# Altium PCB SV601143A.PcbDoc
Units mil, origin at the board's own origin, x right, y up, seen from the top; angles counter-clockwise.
Board outline 3000 x 3000 mil, 4 copper layers (Top Layer, MidLayer1, MidLayer2, Bottom Layer), stack 62 mil thick; 53 components, 12 nets, 84 pads, 38 vias.
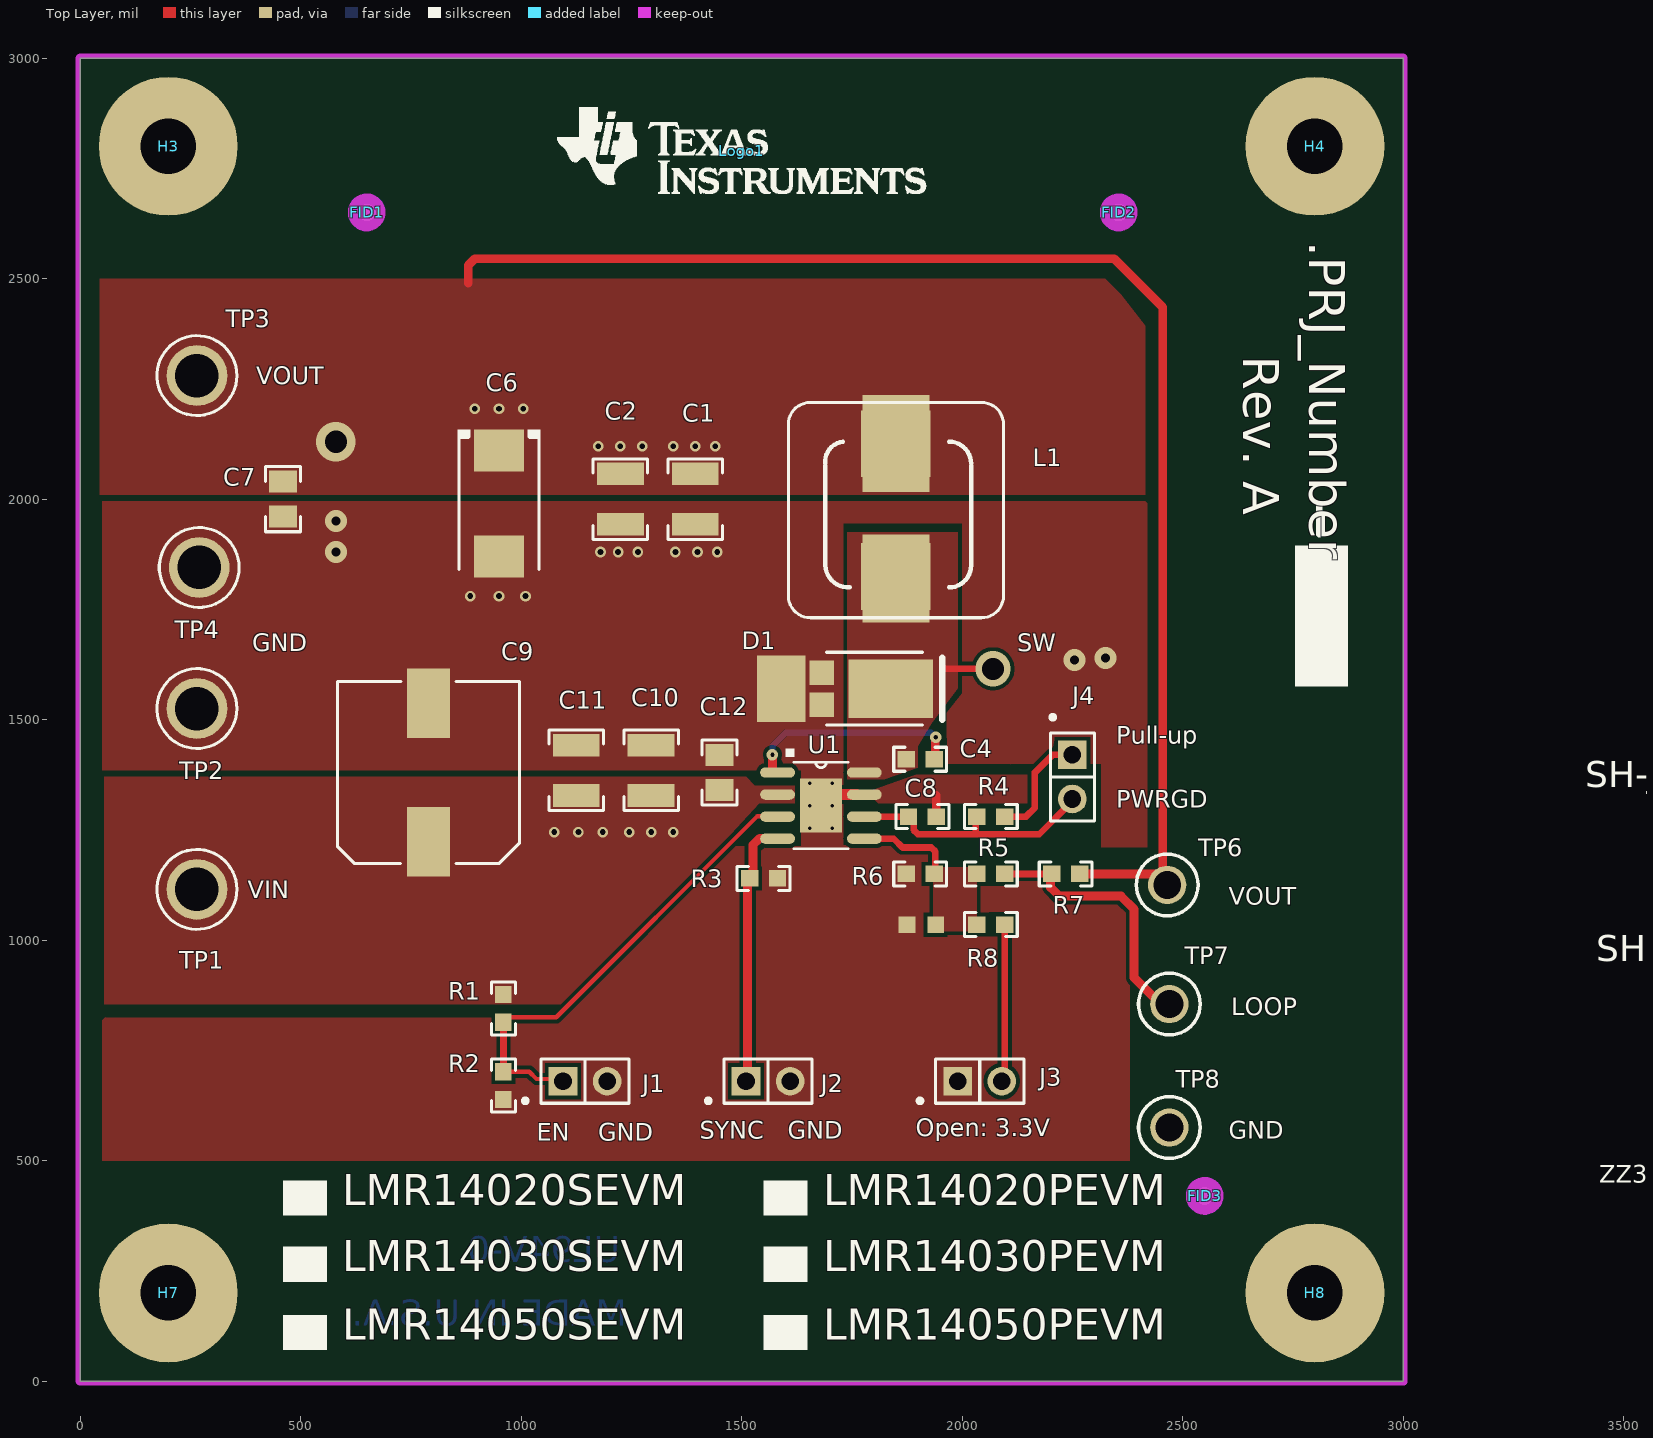
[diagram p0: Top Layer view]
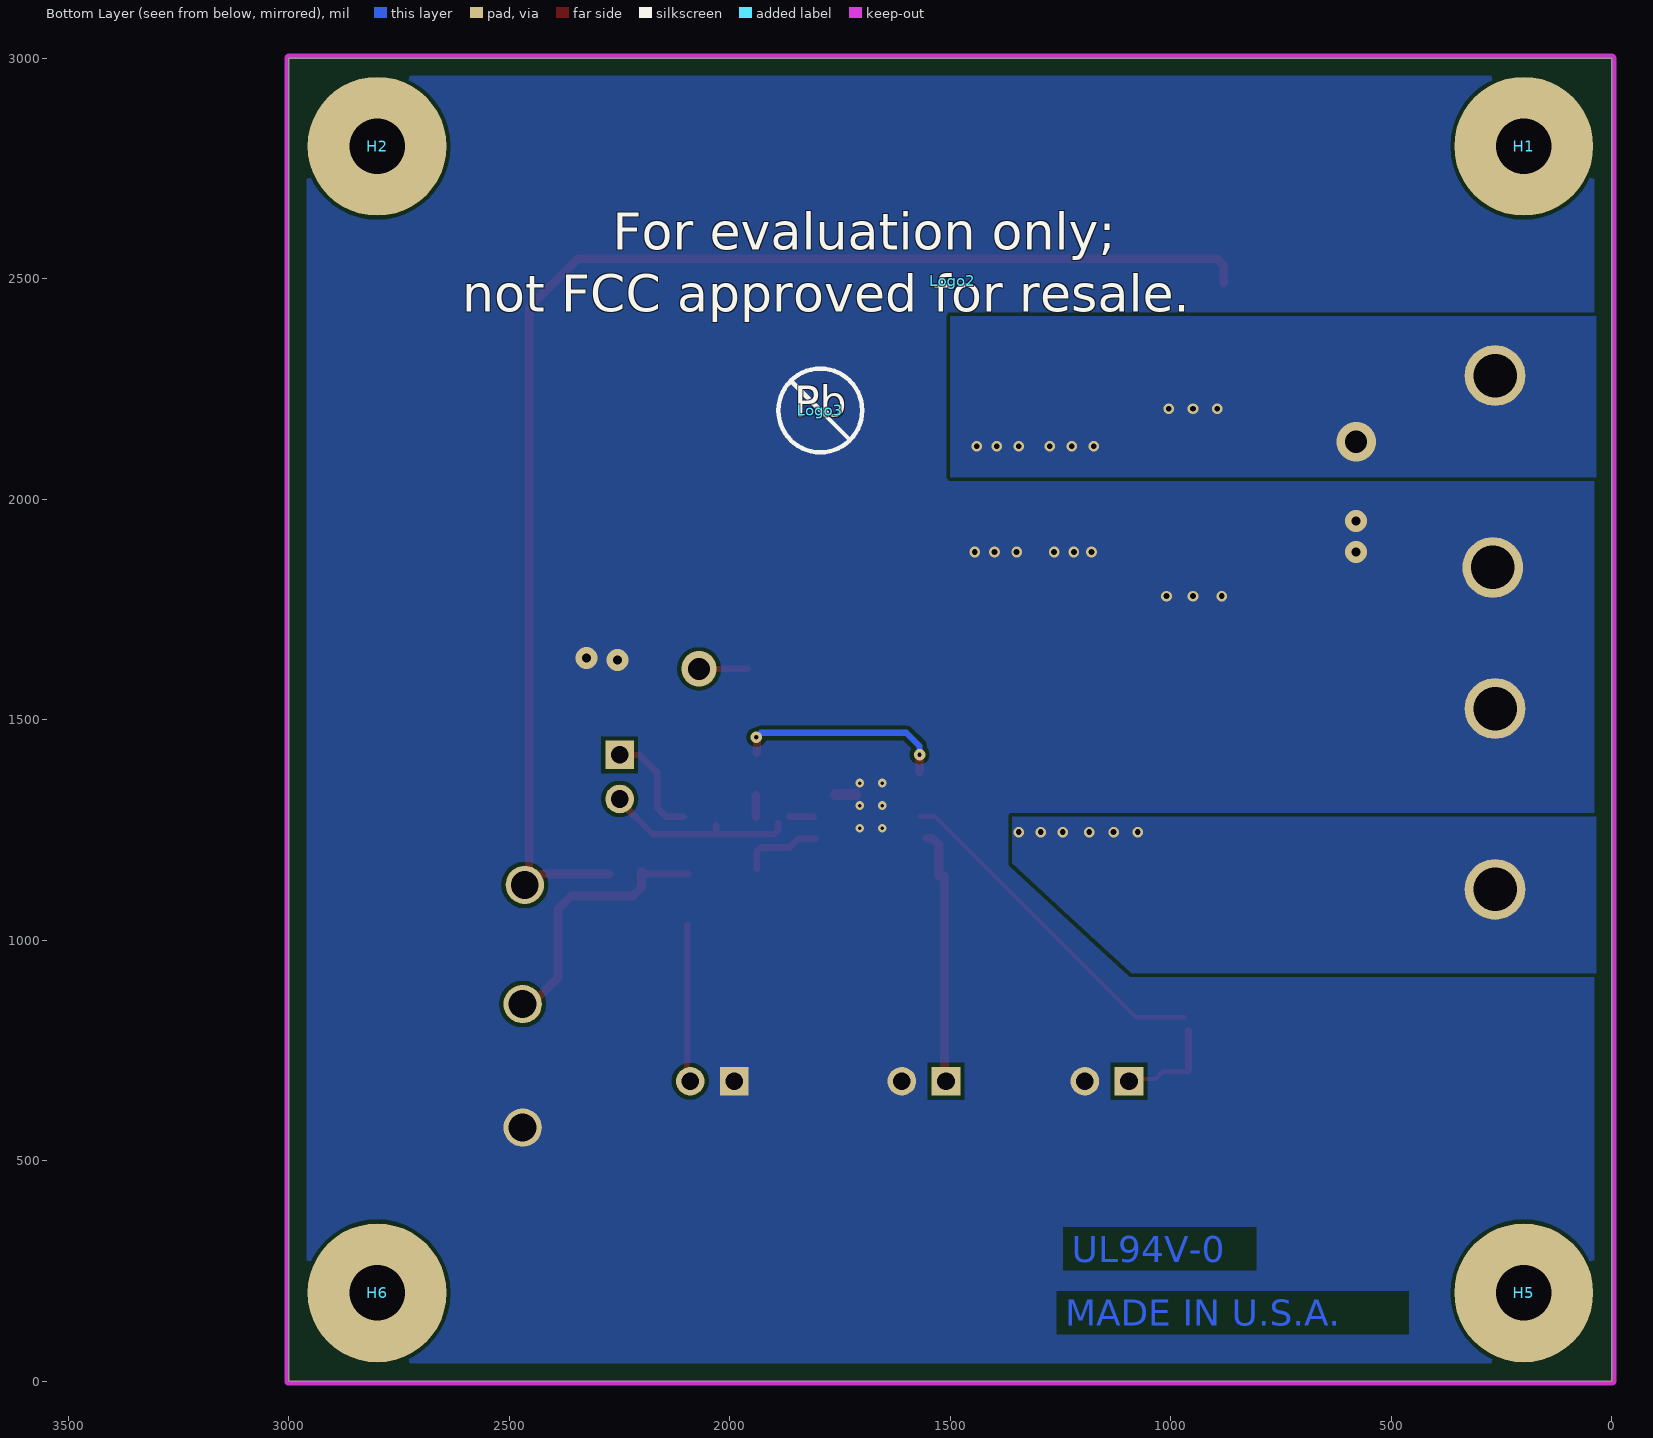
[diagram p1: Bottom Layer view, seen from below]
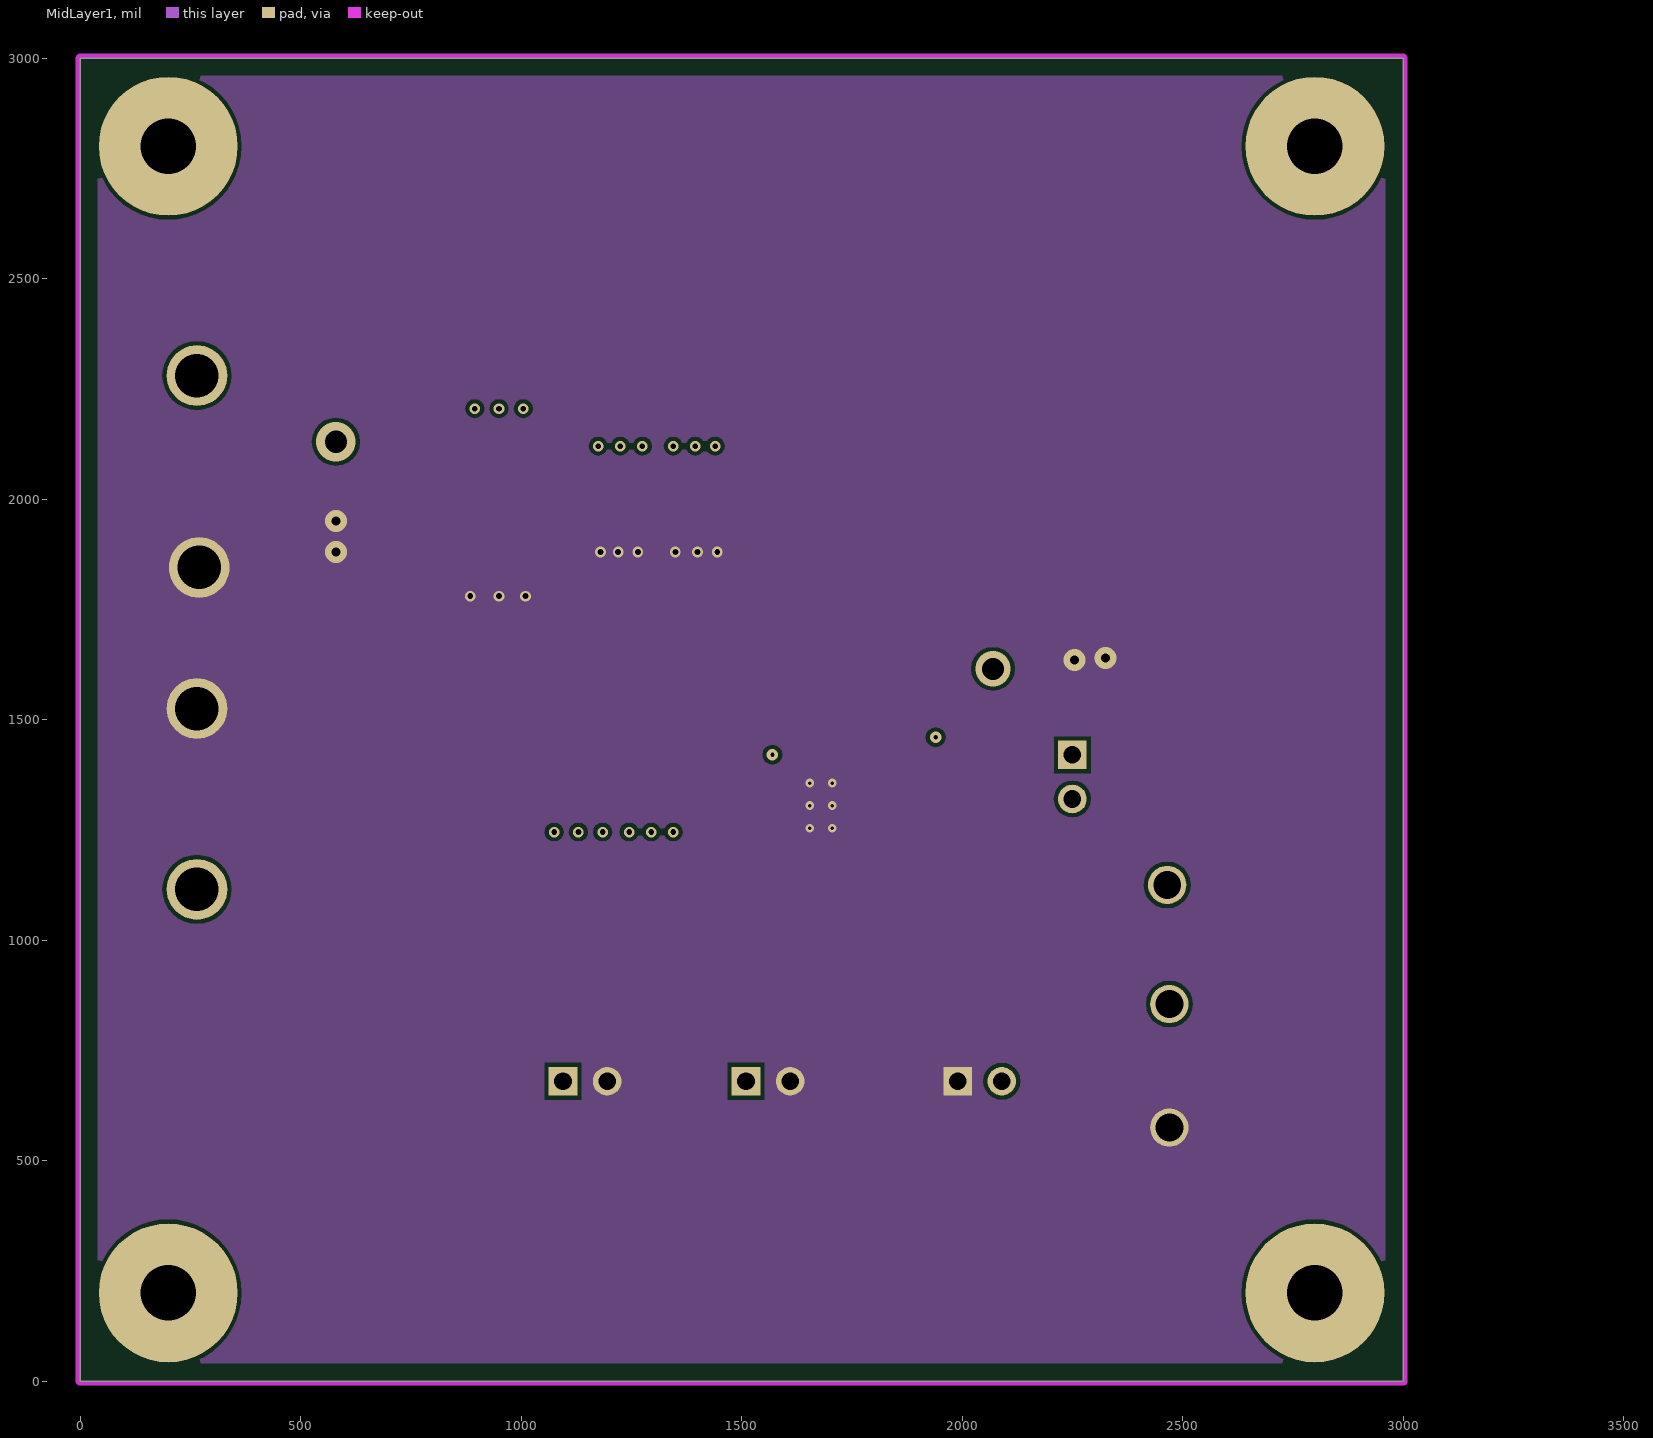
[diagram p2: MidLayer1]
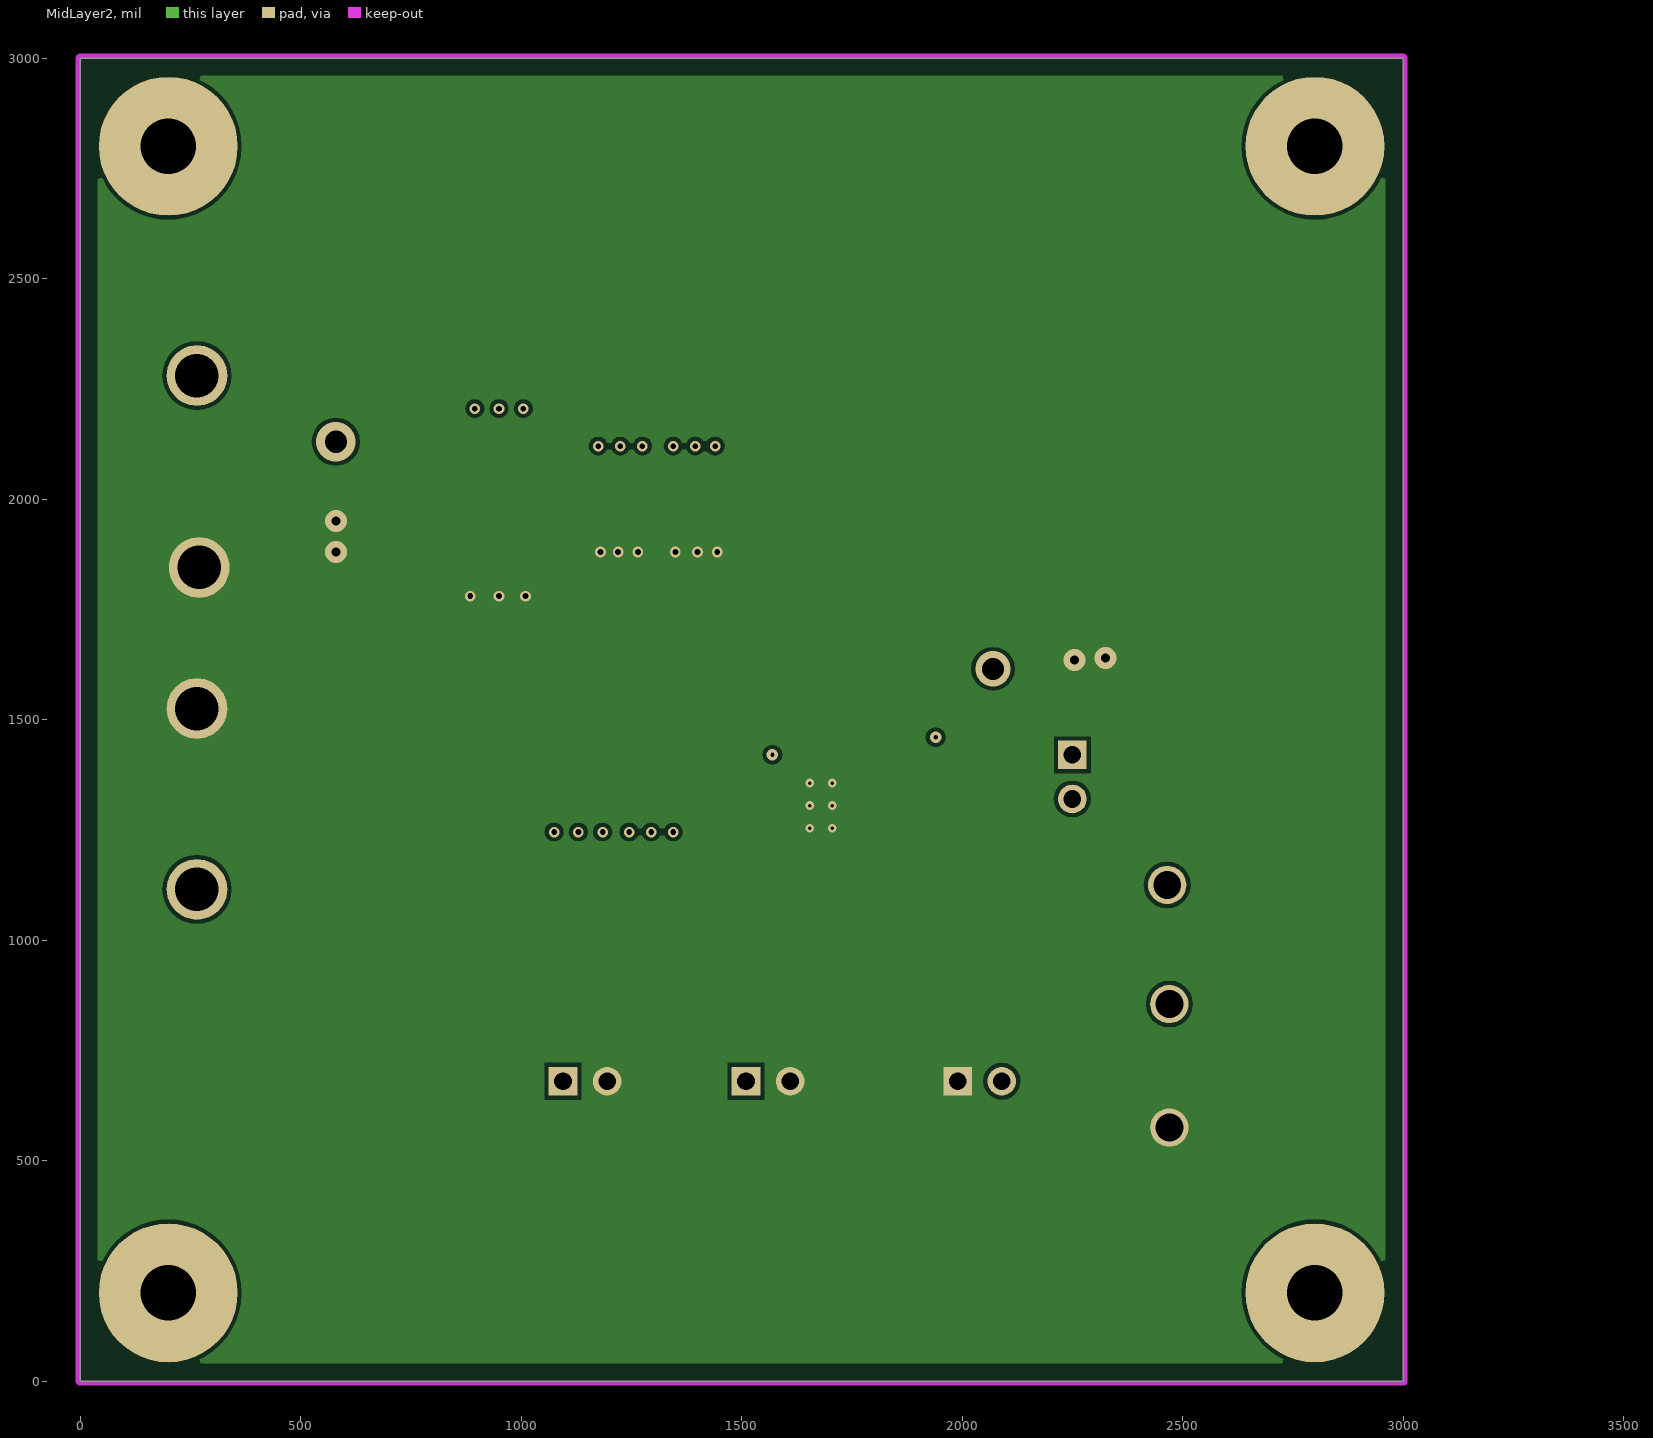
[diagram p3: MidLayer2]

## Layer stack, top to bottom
Top Layer: signal copper 2.8
Dielectric: core 16.9, FR-4, Dk 4.8
MidLayer1: signal copper 2.8
Dielectric: prepreg 17, FR-4, Dk 4.8
MidLayer2: signal copper 2.8
Dielectric: core 16.9, FR-4, Dk 4.8
Bottom Layer: signal copper 2.8

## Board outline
0,0 3000,0 3000,3000 0,3000

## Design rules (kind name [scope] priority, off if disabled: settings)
AcuteAngle [All] p1: minimum=4.50000000000000E+0001 checktracksonly=FALSE
AssemblyTestPointUsage [All] p1: valid=2
Clearance Clearance_1 [InNamedPolygon('Top-VOUT')] p1: gap=15
Clearance Clearance_BoardEdge_MountingHoles [OnCopper and InComponentClass('Mounting Holes') vs IsKeepOut] p2: gap=40
Clearance Clearance_BoardEdge_Poly [OnCopper and InPoly vs IsKeepOut] p3: gap=25
Clearance Clearance_BoardEdge [OnCopper and Not InComponentClass('Logo') and not InComponentClass('FiducialMark') and not InRegion(1000,500,4000,800) vs IsKeepOut] p4: gap=75
Clearance [All] p5: gap=9
ComponentClearance ComponentClearance_Logo [InComponentClass(Logo)] p1: gap=50 collisioncheckmode=3 verticalgap=10 showdistances=FALSE
ComponentClearance ComponentClearance_ScrewToNut [(HasFootprint('NY PMS 440 0025 PH')) vs (HasFootprint('Keystone_1902C'))] p2: gap=5 collisioncheckmode=3 verticalgap=10 showdistances=FALSE
ComponentClearance ComponentClearance_MountingHoles [InComponentClass('Mounting Holes')] p3: gap=0 collisioncheckmode=3 verticalgap=100000 showdistances=FALSE
ComponentClearance ComponentClearance_SmallPassives [HasFootprint('0201*') or HasFootprint('0402*') or HasFootprint('0508') or HasFootprint('0603*') or HasFootprint('0612') or HasFootprint('0805*') or HasFootprint('0815*') or HasFootprint('0830*') or HasFootprint('1206*') or HasFootprint('1210*') or HasFootprint('1808*') or HasFootprint('1812*') or HasFootprint('1825*') or HasFootprint('2010*') or HasFootprint('2220*') or HasFootprint('2225*') or HasFootprint('2512*') or HasFootprint('2728*') or HasFootprint('3518*') vs HasFootprint('0201*') or HasFootprint('0402*') or HasFootprint('0508') or HasFootprint('0603*') or HasFootprint('0612') or HasFootprint('0805*') or HasFootprint('0815*') or HasFootprint('0830*') or HasFootprint('1206*') or HasFootprint('1210*') or HasFootprint('1808*') or HasFootprint('1812*') or HasFootprint('1825*') or HasFootprint('2010*') or HasFootprint('2220*') or HasFootprint('2225*') or HasFootprint('2512*') or HasFootprint('2728*') or HasFootprint('3518*')] p4: gap=20 collisioncheckmode=3 verticalgap=10 showdistances=FALSE
ComponentClearance ComponentClearance_THtoSMT [IsThruComponent vs IsSMTComponent] p5: gap=25 collisioncheckmode=3 verticalgap=100000 showdistances=TRUE
ComponentClearance ComponentClearance_THtoTH [IsThruComponent vs IsThruComponent] p6: gap=15 collisioncheckmode=3 verticalgap=100000 showdistances=TRUE
ComponentClearance [All] p7: gap=0 collisioncheckmode=3 verticalgap=10 showdistances=FALSE
DiffPairsRouting [All] p1: maxlimit=100 minlimit=10 mostfreqgap=10 maxuncoupledlength=1000
FabricationTestPointUsage TestPointUsage [All] p1: valid=2 allowmultiple=FALSE
FabricationTestpoint Testpoint [All] p1: side=3 testpointundercomponent=TRUE minsize=40 maxsize=100 preferedsize=60 minholesize=0 maxholesize=40 preferedholesize=32 testpointgrid=1 allowsidetop=TRUE allowsidebottom=TRUE usegrid=TRUE gridtolerance=0.01
FanoutControl Fanout_LCC [IsLCC] p1: bgadir=Out bgaviamode=Centered fanoutstyle=Auto fanoutdirection=Alternating viagrid=1 // Fanout_LCC (Default Rule)
FanoutControl Fanout_BGA [IsBGA] p2: bgadir=Out bgaviamode=Centered fanoutstyle=Auto fanoutdirection=Alternating viagrid=1 // Fanout_BGA (Default Rule)
FanoutControl Fanout_Default [All] p4: bgadir=Out bgaviamode=Centered fanoutstyle=Auto fanoutdirection=Alternating viagrid=1 // Fanout_Default (Default Rule)
FanoutControl Fanout_Small [(CompPinCount < 5)] p5: bgadir=Out bgaviamode=Centered fanoutstyle=Auto fanoutdirection=OutThenIn viagrid=1 // Fanout_Small (Default Rule)
HoleSize [All] p1: absolutevalues=TRUE maxlimit=251 minlimit=7.8 maxpercent=80.000 minpercent=20.000
MinimumAnnularRing [All] p1: minimumring=5.5
MinimumSolderMaskSliver MinimumSolderMaskSliver_Logo [InComponentClass('Logo') vs InComponentClass('Logo')] p1: minsoldermaskwidth=0.7
MinimumSolderMaskSliver [All] p2: minsoldermaskwidth=5
PlaneConnect [All] p1: planeconnectstyle=Direct reliefexpansion=20 reliefentries=4 reliefconductorwidth=10 reliefairgap=10
PolygonConnect [All] p1: connectstyle=Direct reliefconductorwidth=10 reliefentries=4 polygonreliefangle="90 Angle" airgapwidth=10
RoutingVias [All] p1: holewidth=16 width=34 viastyle="Through Hole" minholewidth=7.8 minwidth=19 maxholewidth=50 maxwidth=90
SMDToCorner [All] p1: distance=30000
SilkToSilkClearance [All] p1: silktosilkclearance=5
SilkscreenOverComponentPads [All] p1: minsilkscreentomaskgap=5
SolderMaskExpansion [All] p1: expansion=1
Width [All] p1: maxlimit=100 minlimit=8 preferedwidth=10 checkconnectedcopper=TRUE
14 further rules are at their usual default settings.

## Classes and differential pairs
component class Shunt: SH-J1 SH-J3
component class Header: J1 J2 J3 J4
component class AssemblyNote: ZZ1 ZZ2 ZZ4 ZZ5
component class FiducialMark: FID1 FID2 FID3
component class Logo: Logo1
component class "Mounting Holes": H3 H4 H7 H8

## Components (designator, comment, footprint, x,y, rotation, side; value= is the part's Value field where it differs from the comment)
C1 "GRM32ER61C476ME15L" 1210 1395,2000 r270 top
C2 "GRM32ER61C476ME15L" 1210 1225,2000 r270 top
C4 "GRM188R71C104KA01D" 0603 1905,1410 r0 top
C6 "16TQC150MYF" 7343-28 950,1990 r270 top
C7 "GRM21BR71E105KA99L" 0805_HV 460,2000 r270 top
C8 "C0603C273K1RACTU" 0603 1910,1280 r0 top
C9 "EEHZA1J560P" SM_RADIAL_10BMM 790,1380 r90 top
C10 "GRM32ER71H475KA88L" 1210 1295,1385 r90 top
C11 "GRM32ER71H475KA88L" 1210 1125,1385 r90 top
C12 "GRM21BR71H224KA01L" 0805_HV 1450,1380 r90 top
D1 "PDS560-13" PowerDI5 1760,1570 r0 top
FID1 "Fiducial" Fiducial10-20 650,2650 r0 top
FID2 "Fiducial" Fiducial10-20 2355,2650 r0 top
FID3 "Fiducial" Fiducial10-20 2550,420 r0 top
H1 "1902C" Keystone_1902C 200,2800 r180 bottom locked
H2 "1902C" Keystone_1902C 2800,2800 r180 bottom locked
H3 "NY PMS 440 0025 PH" "NY PMS 440 0025 PH" 200,2800 r0 top locked
H4 "NY PMS 440 0025 PH" "NY PMS 440 0025 PH" 2800,2800 r0 top locked
H5 "1902C" Keystone_1902C 200,200 r180 bottom locked
H6 "1902C" Keystone_1902C 2800,200 r180 bottom locked
H7 "NY PMS 440 0025 PH" "NY PMS 440 0025 PH" 200,200 r0 top locked
H8 "NY PMS 440 0025 PH" "NY PMS 440 0025 PH" 2800,200 r0 top locked
J1 "TSW-102-07-G-S" TSW-102-07-G-S 1145,680 r0 top
J2 "TSW-102-07-G-S" TSW-102-07-G-S 1560,680 r0 top
J3 "TSW-102-07-G-S" TSW-102-07-G-S 2040,680 r0 top
J4 "TSW-102-07-G-S" TSW-102-07-G-S 2250,1370 r270 top
L1 "744325550" WE-HC6 1850,1975 r90 top
Logo1 "Texas Instruments" TI_Stacked_Overlay_Small 1500,2790 r0 top
Logo2 "FCC disclaimer" FCC_disclaimer_stacked 1495,2495 r180 bottom
Logo3 "Pb-Free Symbol" Pb-Free_Overlay_Medium 1795,2200.98 r180 bottom
R1 "CRCW0603432KFKEA" 0603 960,845 r90 top
R2 "CRCW060386K6FKEA" 0603 960,670 r90 top
R3 "CRCW060359K0FKEA" 0603 1550,1140 r180 top
R4 "CRCW060310K0JNEA" 0603 2065,1280 r180 top
R5 "CRCW060353K6FKEA" 0603 2065,1150 r0 top
R6 "CRCW060315K8FKEA" 0603 1905,1150 r0 top
R7 "CRCW060349R9FKEA" 0603 2235,1150 r0 top
R8 "CRCW060323K7FKEA" 0603 2065,1035 r180 top
SH-J1 "SPC02SYAN" SPC02SYAN 3453,1216 r90 top
SH-J3 "SPC02SYAN" SPC02SYAN 3478,821 r90 top
TP1 "Suggest using a net name here" Keystone1502-2 265,1115 r0 top
TP2 "Suggest using a net name here" Keystone1502-2 265,1525 r0 top
TP3 "Suggest using a net name here" Keystone1502-2 265,2280 r0 top
TP4 "Suggest using a net name here" Keystone1502-2 270,1845 r0 top
TP6 "5010" Keystone5010 2465,1125 r0 top
TP7 "5014" Keystone5014 2470,855 r0 top
TP8 "5011" Keystone5011 2470,575 r0 top
U1 "LMR14050SDDAR" DDA0008E_N 1680,1305 r0 top
ZZ1 "SH-J1 cover one pin only" AssemblyNote 82,3497 r0 top
ZZ2 "SH-J3 on pins 1-2" AssemblyNote 82,3388.11 r0 top
ZZ3 "These assemblies are ESD sensitive, ESD precautions shall be observed." AssemblyNote 3078,241 r90 top
ZZ4 "These assemblies must be clean and free from flux and all contaminants. Use of no clean flux is not acceptable." AssemblyNote 82,3299.56 r0 top
ZZ5 "These assemblies must comply with workmanship standards IPC-A-610 Class 2., unless otherwise specified." AssemblyNote 82,3211 r0 top

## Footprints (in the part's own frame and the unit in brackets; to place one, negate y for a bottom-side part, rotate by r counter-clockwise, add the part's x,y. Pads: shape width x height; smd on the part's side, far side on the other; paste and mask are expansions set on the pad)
0603 [mm] "0603 from SM-752 data"
  rect 1x0.95 smd: 1(-0.8,0) 2(0.8,0)
  silkscreen extent -1.52,-0.69 1.52,0.69, body extent -0.87,-0.47 0.87,0.47, height 0.85
0805_HV [mil] "0805 with 30mil clearance between pads"
  rect 50x63 smd: 1(-40,0) 2(40,0)
  silkscreen extent -74,-40 74,40, body extent -43,-29 43,29, height 43
1210 [mm] "1210 from SM-752 data"
  rect 1.3x2.7 smd: 1(-1.45,0) 2(1.45,0)
  silkscreen extent -2.32,-1.57 2.32,1.57, body extent -1.7,-1.35 1.7,1.35, height 1.35
7343-28 [mm] "Panasonic recommended land pattern for size code D3L"
  rect 2.4x2.9 smd: 1(-3.05,0) 2(3.05,0)
  silkscreen extent -4.25,-2.39 3.8,2.39, body extent -3.8,-2.3 3.8,2.3, height 2.9
AssemblyNote [mil] "Assembly Note"
DDA0008E_N [mm]
  oval 2x0.6 smd: 1(-2.5,1.905) 2(-2.5,0.635) 3(-2.5,-0.635) 4(-2.5,-1.905) 5(2.5,-1.905) 6(2.5,-0.635) 7(2.5,0.635) 8(2.5,1.905)
  rect 2.4x3.1 smd: 9(0,0)
  silkscreen extent -1.58,-2.49 1.58,2.49, body extent -2.98,-2.45 2.98,2.45, height 1.5
FCC_disclaimer_stacked [mil]
Fiducial10-20 [mm]
  round 1 smd mask+0.5: 1(0,0)
  Top Layer keep-out circle w1.178: c0,0 r0.5
Keystone1502-2 [mm] "Double Turret"
  round 3.5 hole 2.5: 1(0,0)
  silkscreen extent -2.3,-2.3 2.3,2.3, body extent -1.6,-1.6 1.59,1.6, height 5.62
Keystone5010 [mil] "Keystone Multipurpose loops"
  round 87 hole 63: 1(0,0)
  silkscreen extent -70,-70 70,70, body extent -63,-63 63,62, height 319
Keystone5011 [mil] "Keystone Multipurpose loops"
  round 87 hole 63: 1(0,0)
  silkscreen extent -70,-70 70,70, body extent -63,-63 63,62, height 319
Keystone5014 [mil] "Keystone Multipurpose loops"
  round 87 hole 63: 1(0,0)
  silkscreen extent -70,-70 70,70, body extent -63,-63 63,62, height 319
Keystone_1902C [mil] "Hex Standoff, 4-40 threaded, nylon"
  round 1 on Mech4: 0(0,0)
  body extent -145,-126 146,126, height 501
"NY PMS 440 0025 PH" [mm] "4-40 nylon screw and mounting hole"
  round 8 hole 3.2: 1(0,0)
  body extent -3.3,-3.3 3.3,3.3, height 2.69
Pb-Free_Overlay_Medium [mil]
  silkscreen extent -95,-95 95,95
PowerDI5 [mm] "Diodes Inc recommended land pattern, ap02001.pdf rev 60"
  rect 1.4x1.39 smd mask+0.025: 1(-1.991,0.92) 2(-1.991,-0.92)
  rect 4.86x3.36 smd: 3(1.991,0)
  silkscreen extent -1.7,-2.1 3.8,2.1, body extent -2.27,-2.03 4.33,2.03, height 1.17
SM_RADIAL_10BMM [mm] "Nichicon 10x10"
  rect 4x2.5 smd: 1(-4,0) 2(4,0)
  silkscreen extent -5.25,-5.25 5.25,5.25, body extent -5.26,-5.26 5.26,5.26, height 10.5
SPC02SYAN [mil] "SULLINS"
  round 1 on Mech3: 0(0,0)
  body extent -98,-47 99,47, height 366
TI_Stacked_Overlay_Small [mil]
  silkscreen extent -418,-98 418,98
TSW-102-07-G-S [mm] "Samtec 100mil, 1x2, 230 mil above insulator"
  rect 1.65x1.65 hole 1.016 mask+0: 1(-1.27,0)
  round 1.65 hole 1.016 mask+0: 2(1.27,0)
  silkscreen extent -3.56,-1.27 2.54,1.27, body extent -2.54,-1.27 2.54,1.27, height 8.38
WE-HC6 [mm] "Wurth Electronik recommended land pattern"
  rect 3.85x4 smd: 1(-3.825,0) 2(3.825,0)
  silkscreen extent -6.2,-6.2 6.2,6.2, body extent -5.77,-5.37 5.75,5.35, height 5

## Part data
C1 C2: "CAP, CERM, 47uF, 16V, +/-20%, X5R, 1210"
C4: "CAP, CERM, 0.1 µF, 16 V, +/- 10%, X7R, 0603"
C6: "CAP, TA, 150 µF, 16 V, +/- 20%, 0.05 ohm, SMD"
C7: "CAP, CERM, 1 µF, 25 V, +/- 10%, X7R, 0805"
C8: "CAP, CERM, 0.027 µF, 100 V, +/- 10%, X7R, 0603"
C9: "CAP, AL, 56 µF, 63 V, +/- 20%, 30 ohm, SMD"
C10 C11: "CAP, CERM, 4.7uF, 50V, +/-10%, X7R, 1210"
C12: "CAP, CERM, 0.22 µF, 50 V, +/- 10%, X7R, 0805"
D1: "Diode, Schottky, 60 V, 5 A, PowerDI5"
FID1 FID2 FID3: "Fiducial mark.  There is nothing to buy or mount."
H1 H2 H5 H6: "Standoff, Hex, 0.5\"L #4-40 Nylon"
H3 H4 H7 H8: "Machine Screw, Round, #4-40 x 1/4, Nylon, Philips panhead"
J1: "Header, 100mil, 2x1, Gold, TH"
J2 J3 J4: "Header, TH, 100mil, 2x1, Gold plated, 230 mil above insulator"
L1: "Inductor, Shielded Drum Core, Superflux, 5.5 µH, 10 A, 0.0112 ohm, SMD"
Logo1: library part TI_Logo, "Texas Instrument Corporate Signature"
Logo2: library part FCC_disclaimer, "FCC_disclaimer"
Logo3: library part Pb-Free
R1: "RES, 432 k, 1%, 0.1 W, 0603"
R2: "RES, 86.6 k, 1%, 0.1 W, 0603"
R3: "RES, 59.0 k, 1%, 0.1 W, 0603"
R4: "RES, 10 k, 5%, 0.1 W, 0603"
R5: "RES, 53.6k ohm, 1%, 0.1W, 0603"
R6: "RES, 15.8 k, 1%, 0.1 W, 0603"
R7: "RES, 49.9 ohm, 1%, 0.1W, 0603"
R8: "RES, 23.7 k, 1%, 0.1 W, 0603"
SH-J1 SH-J3: "Shunt, 100mil, Flash Gold, Black"
TP1 TP2 TP3 TP4: library part 1502-2, "Terminal, Turret, TH, Double"
TP6: "Test Point, TH, Multipurpose, Red"
TP7: "Test Point, Multipurpose, Yellow, TH"
TP8: "Test Point, TH, Multipurpose, Black"
U1: "LMR14050SDDAR, DDA0008E"
ZZ1 ZZ2 ZZ3 ZZ4 ZZ5: library part AssemblyNote

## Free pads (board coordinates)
  rect 110x150 smd mask+1: 0(1590,1570)
  rect 140x200 on Bottom Solder: 0(1680,1305)
  rect 152x200 smd: 0(1850,1820)
  rect 152x220 smd: 0(1850,2125.59)
  rect 38x38 smd: 0(1875,1035) 0(1940,1035)

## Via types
v1: diameter 24/24/24/24 (per signal layer), hole 13, Top Layer to Bottom Layer, 24 vias
v2: diameter 19.68, hole 7.87, Top Layer to Bottom Layer, tented top, 6 vias
v3: diameter 50, hole 20, Top Layer to Bottom Layer, 4 vias
v4: diameter 26/26/26/26 (per signal layer), hole 10, Top Layer to Bottom Layer, 2 vias
v5: diameter 90, hole 50, Top Layer to Bottom Layer, 1 vias
v6: diameter 80, hole 50, Top Layer to Bottom Layer, 1 vias

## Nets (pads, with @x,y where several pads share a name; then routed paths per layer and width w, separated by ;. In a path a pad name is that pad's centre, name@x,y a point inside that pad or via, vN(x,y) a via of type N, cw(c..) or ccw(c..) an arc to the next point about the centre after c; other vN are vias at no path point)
GND: C1.2 C2.2 C6.2 C7.2 C8.2 C9.2 C10.2 C11.2 C12.2 D1.1 D1.2 J1.2 J2.2 J3.1 pad.0@1590,1570 pad.0@1875,1035 R2.1 R3.1 R6.1 TP2.1 TP4.1 TP8.1 U1.7 U1.9 | length 93.5
  Top Layer w20: C8.2 1941.5,1328.5
  Top Layer w25: U1.9@1715,1330 U1.7@1760,1330
  other v1: 885,1780 950,1780 1010,1780 1180,1880 1220,1880 1265,1880 1350,1880 1400,1880 1445,1880
  other v2: 1654.41,1253.82 1705.59,1253.82 1654.41,1305 1705.59,1305 1654.41,1356.18 1705.59,1356.18
  other v3: 2255,1635 2325,1640 580,1880 580,1950
NetC1_1: C1.1 C2.1 C6.1 C7.1 L1.2 pad.0@1850,2125.59 R7.2 TP3.1 TP6.1 | length 3157.3
  Top Layer w20: 880,2490 880,2530 895,2545 2073.75,2545 2345,2545 2455,2435 TP6.1@2455,1130 ; R7.2@2274.45,1150 TP6.1@2460,1150
  other v1: 1175,2120 1225,2120 1275,2120 1345,2120 1395,2120 1440,2120 895,2205 950,2205 1005,2205
  other v5: 580,2130
NetC4_1: C4.1 D1.3 L1.1 pad.0@1850,1820 U1.8 | length 110
  Top Layer w15: 1960,1615 v6(2070,1615)
NetC4_2: C4.2 U1.1 | length 481.1
  Top Layer w20: U1.1@1570,1380.5 v4@1570,1415.5 ; C4.2@1939,1425 v4@1939,1460
  Bottom Layer w13: v4@1940,1455 v4(1940,1460)
  Bottom Layer w14: v4(1570,1420.5) 1570,1440 1600,1470 1930,1470 v4(1940,1460)
NetC8_1: C8.1 J4.2 R4.2 U1.6 | length 479.5
  Top Layer w15: U1.6@1810,1280 C8.1@1865,1280 ; C8.1@1890,1265 1890,1250 1900,1240 2175,1240 J4.2@2245,1310 ; 2030.57,1240 R4.2@2030.57,1261.32
NetC9_1: C9.1 C10.1 C11.1 C12.1 R1.2 TP1.1 U1.2
  other v1: 1075,1245 1130,1245 1185,1245 1245,1245 1295,1245 1345,1245
NetJ1_1: J1.1 R1.1 R2.2 U1.3 | length 1016.6
  Top Layer w10: R2.2 1018.5,701.5 1035,685 J1.1@1090,685 ; R1.1@970,825 1079.65,825 1535.15,1280.5 U1.3@1570,1280.5
  Top Layer w15: R2.2@960,704.43 R1.1@960,795.55
NetJ2_1: J2.1 R3.2 U1.4 | length 569.4
  Top Layer w20: J2.1@1513.5,680 R3.2@1513.5,1145 ; R3.2@1525.55,1145 1525.55,1215.55 1541,1231 U1.4@1553,1231
NetJ3_2: J3.2 R8.1 | length 348.5
  Top Layer w15: J3.2@2096.5,686.5 R8.1
NetJ4_1: J4.1 R4.1 | length 249.9
  Top Layer w15: R4.1@2105,1280 2145,1280 2165,1300 2165,1380 2205,1420 J4.1
NetR5_1: pad.0@1940,1035 R5.1 R6.2 R8.2 U1.5 | length 186.6
  Top Layer w15: U1.5@1805,1230 1845,1230 1865,1210 1930,1210 1939.45,1200.55 R6.2@1939.45,1160.55
NetR5_2: R5.2 R7.1 TP7.1 | length 581
  Top Layer w15: R5.2@2095,1150 R7.1
  Top Layer w20: R7.1@2200.55,1156.3 2200.55,1119.45 2220,1100 2360,1100 2390,1070 2390,915 TP7.1@2440,865
pads on no net: FID1.1 FID2.1 FID3.1 H1.0 H2.0 H3.1 H4.1 H5.0 H6.0 H7.1 H8.1 SH-J1.0 SH-J3.0

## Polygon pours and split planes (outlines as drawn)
NetR5_1 on Top Layer "Top Layer-No Net 5" (solid, pour order 17): 1936.5,1165 1935,1163.11 1935,1020 2030.55,1020 2033.5,1023.72 2033.5,1165
NetC1_1 on Top Layer "Top-VOUT" (solid, remove dead copper, pour order 26): 45,2010 2415,2010 2415,2392.81 2360,2464.27 2325,2500 45,2500
NetC4_1 on Top Layer "Top Layer-No Net 1" (solid, pour order 19): 1740,1925 1990,1925 1990,1571.32 1930.51,1490.28 1900,1440 1900,1391.3 1825,1365 1740,1365
GND on Top Layer "Top Layer-No Net 3" (solid, pour order 29): 1895,1375 2160,1375 2155,1372.05 2155,1310 1810,1310 1800,1320.5 1795,1340
NetC9_1 on Top Layer "Top Layer-No Net" (solid, pour order 16): 1620,1350 1620,1310 1540,1310 1180,925.35 1109.65,855 55,855 55,1370 1510,1370 1530,1350
GND on Top Layer "Top Layer-No Net 4" (solid, remove dead copper, pour order 30): 1715,2000 2420,2000 2420,1210 2315,1210 2315,1400 2110,1400 2113.27,1398.82 1966.02,1400 1965,1515 2000,1560 2000,1945 1715,1945
GND on Top Layer "Top Layer-No Net 2" (solid, remove dead copper, pour order 24): 50,2005 1730,2005 1730,1215 2380,1215 2380,500 50,500 50,825 1074.65,823.35 1459.65,1212.37 1635,1212.37 1635,1385 50,1385
NetC1_1 on Bottom Layer "Bottom Layer-No Net 1" (solid, pour order 25): 35,2415 1500,2415 1500,2050 35,2050
NetC9_1 on Bottom Layer "Bottom Layer-No Net" (solid, pour order 22): 35,1280 35,925 1088.94,925 1360,1170 1360,1280
GND on Bottom Layer "Bottom Layer-GND" (solid, remove dead copper, pour order 23): 40,2960 2960,2960 2960,40 40,40
GND on MidLayer1 "MidLayer1-GND" (solid, remove dead copper, pour order 18): 40,2960 2960,2960 2960,40 40,40
GND on MidLayer2 "MidLayer2-GND" (solid, remove dead copper, pour order 20): 40,2960 40,40 2960,40 2960,2960

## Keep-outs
Keep-Out Layer:
  lines w10: -5,0 ccw(c0,0) 0,-5 ; -5,0 ccw(c0,0) 0,-5 ; -5,0 -5,3000 ; -5,3000 cw(c0,3000) 0,3005 ; -5,3000 cw(c0,3000) 0,3005 ; 0,-5 3000,-5 ; 0,3005 3000,3005 ; 3000,-5 ccw(c3000,0) 3005,0 ; 3000,-5 ccw(c3000,0) 3005,0 ; 3000,3005 cw(c3000,3000) 3005,3000 ; 3000,3005 cw(c3000,3000) 3005,3000 ; 3005,0 3005,3000
  text ".Layer_Name" at 577,-858.49 h60

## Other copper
Top Layer:
  text ".Layer_Name" at 577,-858.49 h60
MidLayer1:
  text ".Layer_Name" at 577,-858.49 h60
MidLayer2:
  text ".Layer_Name" at 577,-858.49 h60
Bottom Layer:
  text "UL94V-0" at 1225,270 h60
  text "MADE IN U.S.A." at 1240,125 h60
  text ".Layer_Name" at 577,-858.49 h60

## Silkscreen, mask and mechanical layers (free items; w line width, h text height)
Top Overlay:
  rectangle: 1550,70 1650,150
  rectangle: 1550,225 1650,305
  rectangle: 1550,375 1650,455
  rectangle: 460,375 560,455
  rectangle: 460,225 560,305
  rectangle: 460,70 560,150
  rectangle: 2755,1575 2875,1895
  rectangle: 1600,1415 1620,1435
  lines w10: 1689.65,2075 1689.65,2018.66 1689.65,1905.98 1689.65,1849.65 ccw(c1742.32,1852.32) 1745,1799.65 ; 1689.65,2080 cw(c1734.82,2084.82) 1730,2130 ; 1970.35,1799.65 ccw(c1970.35,1849.65) 2020.35,1849.65 2020.35,2075 ; 1970.35,2130.35 cw(c1970.35,2080.35) 2020.35,2080.35
  lines w15: 1955,1500 1955,1640 ; 2810,1920 2810,1985
  text ".PRJ_Number" at 2760,2585 h140 r270
  text "Rev. A" at 2610,2325 h140 r270
  text "VOUT" at 400,2260 h40
  text "GND" at 390,1655 h40
  text "SW" at 2125,1655 h40
  text "Pull-up" at 2350,1445 h40
  text "PWRGD" at 2350,1300 h40
  text "VIN" at 380,1095 h40
  text "VOUT" at 2605,1080 h40
  text "LOOP" at 2610,830 h40
  text "Open: 3.3V" at 1895,555 h40
  text "SYNC" at 1405,550 h40
  text "GND" at 1605,550 h40
  text "GND" at 2605,550 h40
  text "EN" at 1035,545 h40
  text "GND" at 1175,545 h40
  text "LMR14020SEVM" at 595,375 h120
  text "LMR14020PEVM" at 1685,375 h120
  text "LMR14030SEVM" at 595,225 h120
  text "LMR14030PEVM" at 1685,225 h120
  text "LMR14050SEVM" at 595,70 h120
  text "LMR14050PEVM" at 1685,70 h120
  text ".Layer_Name" at 577,-858.49 h60
Bottom Overlay:
  text ".Layer_Name" at 577,-858.49 h60
Top Paste:
  text ".Layer_Name" at 577,-858.49 h60
Bottom Paste:
  text ".Layer_Name" at 577,-858.49 h60
Top Solder:
  text ".Layer_Name" at 577,-858.49 h60
  text ".Layer_Name" at 577,-858.49 h60
Bottom Solder:
  text ".Layer_Name" at 577,-858.49 h60
Drill Guide:
  text ".Layer_Name" at 577,-858.49 h60
M1 Board Outline:
  the board outline again, w10
  text ".Layer_Name" at 577,-858.49 h60
M2 Board Dimensions:
  rectangle: 124.5,-410.5 499.5,-285.5
  rectangle: -0.5,-285.5 124.5,-160.5
  lines w7: -0.5,-285.5 999.5,-285.5 ; 124.5,-410.5 124.5,-160.5 ; 249.5,-410.5 249.5,-160.5 ; 499.5,-410.5 499.5,-160.5 ; 749.5,-410.5 749.5,-160.5 ; -0.5,-410.5 -0.5,-160.5 999.5,-160.5 999.5,-410.5 -0.5,-410.5
  lines w10: -0.5,-475.5 -0.5,-455.5 ; 59.5,-485.5 -0.5,-465.5 ; 59.5,-445.5 -0.5,-465.5 ; 223.58,-465.5 -0.5,-465.5 ; 775.42,-465.5 999.5,-465.5 ; 939.5,-485.5 999.5,-465.5 ; 939.5,-445.5 999.5,-465.5 ; 999.5,-475.5 999.5,-455.5
  text "1000 (mil)" at 233.58,-501.49 h60
  text ".Layer_Name" at 577,-858.49 h60
M3 3D STEP Top:
  text ".Layer_Name" at 577,-858.49 h60
M4 3D STEP Bottom:
  text ".Layer_Name" at 577,-858.49 h60
M5 Assembly Top:
  lines w10: -292,-930.17 6308,-930.17 ; -292,-726.83 6310,-726.83 ; -292,-523.5 -292,-1133.5 3713,-1133.5 6310,-1133.5 6310,-523.5 -291.5,-523.5 -291.5,-1133.5 1284,-1133.5 ; 2173,-1133.5 2173,-523.5 ; 3440,-726.83 3440,-523.5 ; 4280,-726.83 4280,-523.5 ; 4902,-1140 4902,-937.17
  text "COMPONENTS MARKED 'DNP' SHOULD NOT BE POPULATED, AND MAY NOT BE IN BILL OF MATERIALS" at 1153.5,-318.5 h60
  text "ASSEMBLY VARIANT:" at 1153,-434 h60
  text ".VariantName" at 2189,-434 h60
  text "PCB VIEWED FROM TOP SIDE" at -228.5,-655.67 h60
  text "BOARD #:" at 2248,-655.67 h60
  text ".PRJ_Number" at 2793.5,-655.67 h60
  text "REV:" at 3638,-655.67 h60
  text ".PCB_Rev" at 3929.5,-655.67 h60
  text "SVN REV:" at 4476,-655.67 h60
  text ".VersionControl_RevNumber" at 4982,-655.67 h60
  text "IGNORE ->" at -228.5,-858.49 h60
  text "PLOT NAME =" at -228.5,-1064.34 h60
  text ".plot_File_Name" at 577,-1064.34 h60
  text "GENERATED    :" at 2250,-1064.34 h60
  text ".Print_Date" at 3119.5,-1064.34 h60
  text ".Print_Time" at 3848.5,-1064.34 h60
  text "TEXAS INSTRUMENTS" at 5113,-1064.34 h60
M6 Assembly Bottom:
  lines w10: -292.5,-727.33 6309.5,-727.33 ; -290.5,-930.67 6309.5,-930.67 ; 1115.5,-1140.5 1115.5,-937.67 ; 1737.5,-727.33 1737.5,-524 ; 2577.5,-727.33 2577.5,-524 ; 3844.5,-1134 3844.5,-524 ; 4733.5,-1134 6309,-1134 6309,-524 -292.5,-524 -292.5,-1134 2304.5,-1134 6309.5,-1134 6309.5,-524
  text "COMPONENTS MARKED 'DNP' SHOULD NOT BE POPULATED, AND MAY NOT BE IN BILL OF MATERIALS" at 6102,-318 h60
  text ".VariantName" at 5058,-434 h60
  text "ASSEMBLY VARIANT:" at 6097,-434 h60
  text ".VersionControl_RevNumber" at 1035.5,-656.17 h60
  text "SVN REV:" at 1541.5,-656.17 h60
  text ".PCB_Rev" at 2088,-656.17 h60
  text "REV:" at 2379.5,-656.17 h60
  text ".PRJ_Number" at 3224,-656.17 h60
  text "BOARD #:" at 3769.5,-656.17 h60
  text "PCB VIEWED FROM BOTTOM SIDE" at 6246,-656.17 h60
  text "IGNORE ->" at 2547.85,-858.49 h60
  text "TEXAS INSTRUMENTS" at 904.5,-1064.84 h60
  text ".Print_Time" at 2169,-1064.84 h60
  text ".Print_Date" at 2898,-1064.84 h60
  text "GENERATED    :" at 3767.5,-1064.84 h60
  text ".plot_File_Name" at 5440.5,-1064.84 h60
  text "PLOT NAME =" at 6246,-1064.84 h60
M9 Title Sheet:
  drawing of 57 lines, arcs and shapes, not listed
  text "1" at 739.84,8036.5 h70
  text "2" at 3235.5,8036.5 h70
  text "3" at 5724.84,8036.5 h70
  text "4" at 8231.51,8036.5 h70
  text "5" at 10730.5,8036.5 h70
  text "6" at 13235.5,8036.5 h70
  text "A" at -416.5,6893.5 h70
  text "A" at 14383.5,6893.5 h70
  text "B" at -416.5,4513.5 h70
  text "B" at 14383.5,4513.5 h70
  text "C" at -416.5,2138.5 h70
  text "C" at 14383.5,2138.5 h70
  text "PROJECT TITLE:" at 11343.5,277.5 h45
  text ".PRJ_Title" at 11393.5,144.17 h70
  text "DESIGNED FOR:" at 11343.5,-23.5 h45
  text ".PRJ_Customer" at 11393.5,-163.5 h70
  text "D" at -416.5,-231.5 h70
  text "D" at 14383.5,-231.5 h70
  text "FILE NAME:" at 11343.5,-323.5 h45
  text ".PCB_File_Name_No_Path" at 11393.5,-443.5 h70
  text "Texas Instruments (TI) and/or its licensors do not warrant the accuracy or completeness of this specification" at 6374,-605.34 h45
  text "ENGINEER:" at 11343.5,-613.5 h45
  text "LAYOUT BY:" at 12848.5,-613.5 h45
  text "or any information contained therein. TI and/or its licensors do not warrant that this design will meet" at 6329.01,-718 h45
  text ".PRJ_Engineer" at 11393.5,-768.49 h70
  text ".PCB_Layout" at 12899,-768.49 h70
  text "the specifications, will be suitable for your application or fit for any particular purpose, or will operate in" at 6329.01,-830.67 h45
  text ".Layer_Name" at 577,-858.49 h60
  text "ALTIUM DESIGNER VERSION:" at 12848.5,-923.5 h45
  text "an implementation. TI and/or its licensors do not warrant that the design is production worthy. You should" at 6329.01,-943.33 h45
  text "completely validate and test your design implementation to confirm the system functionality for your application." at 6374,-1056 h45
  text ".print_Scale" at 11393.5,-1056.83 h70
  text ".Application_BuildNumber" at 12899,-1056.83 h70
  text "1" at 739.84,-1263.5 h70
  text "2" at 3235.5,-1263.5 h70
  text "3" at 5724.84,-1263.5 h70
  text "4" at 8231.51,-1263.5 h70
  text "5" at 10730.5,-1263.5 h70
  text "6" at 13235.5,-1263.5 h70
M10 Fab Notes:
  drawing of 203 lines, arcs and shapes, not listed
  text "DESIGN INFORMATION" at 12381.02,6810 h60
  text "(REFER ALSO ARRAY/PANEL PROFILING INFORMATION)" at 12019.46,6648.29 h60
  text "BOARD SIZE" at 11333.46,6644 h60
  text "3000MIL" at 11795.78,6516.18 h60
  text "X" at 12301.46,6516.18 h60
  text "3000MIL" at 12532.78,6516.18 h60
  text "Number of Layers :" at 11736.46,6319 h60
  text "4" at 12831.27,6309 h60
  text "MIN. TRACK WIDTH:" at 11736.46,6180 h60
  text "8" at 12832.7,6180 h60
  text "MIL" at 12987.46,6180 h60
  text "MIN. CLEARANCE:" at 11736.46,6048 h60
  text "8" at 12832.7,6048 h60
  text "MIL" at 12987.46,6048 h60
  text "MIN. VIA PAD SIZE:" at 11736.46,5916 h60
  text "22" at 12802.71,5916 h60
  text "MIL" at 12987.46,5916 h60
  text "0.05mm (2MIL)" at 12431.46,5774.29 h60
  text "MINIMUM ANNULAR RING" at 11407.23,5770 h60
  text "EXTERNAL" at 13139.46,5770 h60
  text "PER" at 11607.23,5652 h60
  text "IPC-D-275 CLASS 2 LEVEL C" at 11827.23,5652 h60
  text "MIL, HOLES" at 13315.46,5539.71 h60
  text "+/-" at 12923,5539 h60
  text "+/-" at 13777,5539 h60
  text "REGISTRATION TOLERANCES:" at 11407.23,5534 h60
  text "METAL" at 12607,5534 h60
  text "5" at 13183.2,5534 h60
  text "3" at 14016.2,5534 h60
  text "MIL" at 14132.46,5534 h60
  text "MATERIAL:" at 11332.46,5324.54 h60
  text "X" at 11615,5185 h60
  text "FR-4 High Tg" at 12318.9,5184.21 h60
  text "FR-4" at 11793.46,5175.64 h60
  text "OTHER" at 13241.46,5175.64 h60
  text "62 MIL (1.6mm) +/-10%" at 12073.56,5012.92 h60
  text "THICKNESS:" at 11407.23,5008.64 h60
  text "X" at 11945.4,5008.64 h60
  text "OTHER" at 13358.46,5008.64 h60
  text "TOLERANCE:" at 11407.23,4850.64 h60
  text "X" at 12246.53,4850.64 h60
  text "ANSI IPC-6012 TYPE 3 CLASS 2" at 12433.48,4850.64 h60
  text "OTHER +/-" at 12433.46,4694.64 h60
  text "BOW & TWIST:" at 11407.23,4537.64 h60
  text "X" at 12246.53,4537.64 h60
  text "ANSI IPC-6012 TYPE 3 CLASS 2" at 12433.48,4537.64 h60
  text "OTHER +/-" at 12433.46,4379.13 h60
  text "COPPER THICKNESS (FINISHED):" at 11332.46,4243.64 h60
  text "1.4MIL (1oz)" at 12212.46,4090.92 h60
  text "2MIL (1.4oz)" at 12979.46,4090.92 h60
  text "2.8MIL (2oz)" at 13706.46,4090.92 h60
  text "OUTER:" at 11689.46,4086.64 h60
  text "X" at 13580,4085 h60
  text "1.4MIL (1oz)" at 12562.46,3933.92 h60
  text "2.8MIL (2oz)" at 13406.46,3933.92 h60
  text "INNER SIGNAL:" at 11689.46,3929.64 h60
  text "X" at 13275,3930 h60
  text "DRILLING:" at 11332.46,3790.64 h60
  text "REFERENCE:" at 11407.23,3673.64 h60
  text "X" at 12055.46,3673.64 h60
  text "AS SHOWN" at 12242.46,3673.64 h60
  text "X" at 12956.46,3673.64 h60
  text "NC_DRILL FILES" at 13093.46,3673.64 h60
  text "PTH MIN COPPER THICKNESS:" at 11407.23,3515.64 h60
  text "X" at 12757.46,3515.64 h60
  text "1MIL" at 12894.46,3515.64 h60
  text "OTHER" at 13391.46,3515.64 h60
  text "BOARD FINISH:" at 11332.46,3356.64 h60
  text "SILKSCREEN:" at 11487.68,3238.64 h60
  text "X" at 12436.46,3238.64 h60
  text "TOP" at 12562.46,3238.64 h60
  text "X" at 12946.46,3238.64 h60
  text "BOTTOM" at 13073.46,3238.64 h60
  text "SILKSCREEN COLOR:" at 11487.68,3071.64 h60
  text "X" at 12435.42,3071.64 h60
  text "WHITE" at 12562.46,3071.64 h60
  text "OTHER" at 13073.46,3071.64 h60
  text "SOLDER RESIST COLOR:" at 11487.68,2901.64 h60
  text "X" at 12055.42,2742.44 h60
  text "GREEN" at 12182.46,2742.44 h60
  text "BLUE" at 12773.46,2742.44 h60
  text "OTHER" at 13311.46,2742.44 h60
  text "IMMERSION GOLD (ENIG)" at 12393.46,2553.92 h60
  text "X" at 13485.42,2552.44 h60
  text "SURFACE FINISH:" at 11332.46,2549.64 h60
  text "Pb-FREE HASL" at 13625.75,2549.64 h60
  text "OTHER" at 12393.46,2392.64 h60
  text "ARRAY/PANEL:" at 11332.46,2213.64 h60
  text "CUT AND TRIM PER MECH LAYER 1" at 12393.46,2209.35 h60
  text "N.C. ROUTE" at 12393.46,2057.64 h60
  text "X" at 13072.46,2057.64 h60
  text "V. SCORE" at 13259.46,2057.64 h60
  text "CERTIFICATION:" at 11332.46,1920.64 h60
  text "MATERIALS AND WORKMANSHIP FOR ALL PCBS" at 12057.46,1920.64 h60
  text "TO MEET OR EXCEED THE REQUIREMENTS OF:" at 12057.46,1822.64 h60
  text "X" at 11683.96,1686.13 h60
  text "ANSI IPC-A-600F CLASS ->" at 11822.96,1686.13 h60
  text "X" at 13462.02,1686.13 h60
  text "2" at 13580.96,1686.14 h60
  text "1" at 13265.96,1684.64 h60
  text "3" at 13934.96,1684.64 h60
  text "X" at 11686.02,1526.64 h60
  text "UL 94V-0" at 11822.96,1526.64 h60
  text "X" at 12498.02,1526.64 h60
  text "RoHS" at 12634.96,1526.64 h60
  text "OTHER" at 13279.36,1526.64 h60
  text "PER ORDER" at 13676.42,1526.64 h60
  text "ADDITIONAL REQUIREMENTS:" at 11332.46,1385.64 h60
  text "MICROSECTION:" at 11407.23,1270.64 h60
  text "YES" at 12312.96,1270.64 h60
  text "REQUIRED" at 13174.46,1114.49 h60
  text "BARE BOARD ELEC. TEST:" at 11407.23,1111.64 h60
  text "NONE" at 12712.96,1111.64 h60
  text "X" at 13047.46,1111.64 h60
  text "PER ORDER" at 13766.46,1111.64 h60
  text "MANUFACTURER'S ID/LOGO:" at 11407.23,954.64 h60
  text "RAIL" at 12872.96,950.35 h60
  text "METAL" at 13364.77,950.35 h60
  text "SILK" at 13876.46,950.35 h60
  text "X" at 13732.46,945.35 h60
  text ".Layer_Name" at 577,-858.49 h60
M11 Gerber Information:
  lines w10: -292,-930.17 6308,-930.17 ; -292,-726.83 6310,-726.83 ; -292,-523.5 -292,-1133.5 3713,-1133.5 6310,-1133.5 6310,-523.5 -291.5,-523.5 -291.5,-1133.5 1284,-1133.5 ; 2173,-1133.5 2173,-523.5 ; 3440,-726.83 3440,-523.5 ; 4280,-726.83 4280,-523.5 ; 4902,-1140 4902,-937.17
  text "ALL ARTWORK VIEWED FROM TOP SIDE" at -228.5,-655.67 h60
  text "BOARD #:" at 2248,-655.67 h60
  text ".PRJ_Number" at 2793.5,-655.67 h60
  text "REV:" at 3638,-655.67 h60
  text ".PCB_Rev" at 3929.5,-655.67 h60
  text "SVN REV:" at 4476,-655.67 h60
  text ".VersionControl_RevNumber" at 4982,-655.67 h60
  text "LAYER NAME =" at -228.5,-858.49 h60
  text "PLOT NAME =" at -228.5,-1064.34 h60
  text ".plot_File_Name" at 577,-1064.34 h60
  text "GENERATED    :" at 2250,-1064.34 h60
  text ".Print_Date" at 3119.5,-1064.34 h60
  text ".Print_Time" at 3848.5,-1064.34 h60
  text "TEXAS INSTRUMENTS" at 5113,-1064.34 h60
M12 Stackup:
  lines w6: 11370,7683 14200,7683 ; 11370,7795.6 14200,7795.6 ; 11310,6981 ccw(c11346,6981) 11346,6945 14224,6945 ccw(c14224,6981) 14260,6981 14260,7889 ccw(c14224,7889) 14224,7925 11346,7925 ccw(c11346,7889) 11310,7889 11310,6981
  text "Layer Stack Up Detail for: SV601143A.PcbDoc" at 11370,7824.1 h49
  text "Layer" at 11370,7753.6 h26
  text "Gerber" at 12070.2,7753.6 h26
  text "Copper" at 12424.65,7753.6 h26
  text "Dielectric" at 12821.55,7753.6 h26
  text "Dielectric" at 13236.64,7753.6 h26
  text "Dielectric" at 13756.9,7753.6 h26
  text "Name" at 11370,7701.6 h26
  text "Document" at 12070.2,7701.6 h26
  text "Thickness" at 12424.65,7701.6 h26
  text "Height" at 12821.55,7701.6 h26
  text "Material" at 13236.64,7701.6 h26
  text "Type" at 13756.9,7701.6 h26
  text "Top Solder Mask" at 11370,7628.96 h36
  text "(.GTS)" at 12070.2,7628.96 h36
  text "0.4mil" at 12821.55,7628.96 h36
  text "Solder Resist" at 13236.64,7628.96 h36
  text "Top Layer" at 11370,7526.88 h36
  text "(.GTL)" at 12070.2,7526.88 h36
  text "2.8mil" at 12424.65,7526.88 h36
  text "19mil" at 12821.55,7475.83 h36
  text "FR-4" at 13236.64,7475.83 h36
  text "Core" at 13756.9,7475.83 h36
  text "MidLayer1" at 11370,7424.79 h36
  text "(.G1)" at 12070.2,7424.79 h36
  text "2.8mil" at 12424.65,7424.79 h36
  text "18.4mil" at 12821.55,7373.75 h36
  text "FR-4" at 13236.64,7373.75 h36
  text "PrePreg" at 13756.9,7373.75 h36
  text "MidLayer2" at 11370,7322.71 h36
  text "(.G2)" at 12070.2,7322.71 h36
  text "2.8mil" at 12424.65,7322.71 h36
  text "19mil" at 12821.55,7271.67 h36
  text "FR-4" at 13236.64,7271.67 h36
  text "Core" at 13756.9,7271.67 h36
  text "Bottom Layer" at 11370,7220.63 h36
  text "(.GBL)" at 12070.2,7220.63 h36
  text "2.8mil" at 12424.65,7220.63 h36
  text "Bottom Solder Mask" at 11370,7118.54 h36
  text "(.GBS)" at 12070.2,7118.54 h36
  text "0.4mil" at 12821.55,7118.54 h36
  text "Solder Resist" at 13236.64,7118.54 h36
  text ".Layer_Name" at 577,-858.49 h60
M13 Component Bodies Top:
  text ".Layer_Name" at 577,-858.49 h60
M14 Component Bodies Bottom:
  text ".Layer_Name" at 577,-858.49 h60
M15 Courtyards Top:
  text ".Layer_Name" at 577,-858.49 h60
M16 Courtyards Bottom:
  text ".Layer_Name" at 577,-858.49 h60
Drill Drawing:
  text ".legend" at 5122.5,725.5 h60
  text "Drill Table" at 5147.5,540.5 h60
  text ".Layer_Name" at 577,-858.49 h60

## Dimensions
0,0 to 3000,0 on M2 Board Dimensions
0,0 to 0,3000 on M2 Board Dimensions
